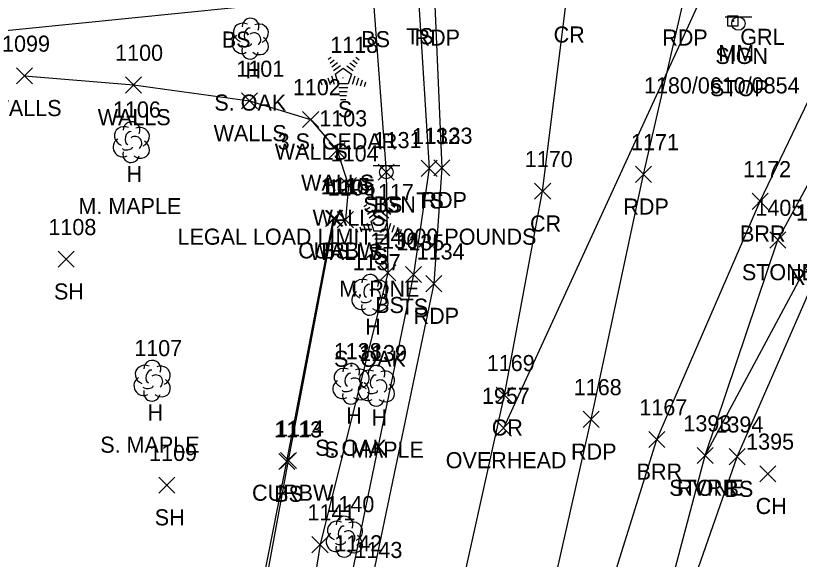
# Model space of a CAD drawing. Extents: x 1600395 to 1603269, y 874955 to 877143.
# Drawn here: x 1601626.7 to 1601724, y 875112.5 to 875180 of the extents above; entities that cross this region are included whole.
import ezdxf

# ---------------------------------------------------------------- set-up
doc = ezdxf.new("R2010")
doc.units = 0
for name, color, linetype in [('L_A', 7, 'Continuous'), ('L_C', 7, 'Continuous'), ('L_I', 7, 'Continuous'), ('L_TIC', 7, 'Continuous'), ('LABL', 7, 'Continuous'), ('LASF', 7, 'Continuous'), ('LAWE', 7, 'Continuous'), ('LELB', 7, 'Continuous'), ('LTC', 7, 'Continuous'), ('LTD', 7, 'Continuous'), ('LWS', 7, 'Continuous'), ('P_A', 7, 'Continuous'), ('P_I', 7, 'Continuous'), ('P_TIC', 7, 'Continuous'), ('PET', 7, 'Continuous'), ('PRC', 7, 'Continuous'), ('R_A', 7, 'Continuous'), ('R_I', 7, 'Continuous'), ('R_TIC', 7, 'Continuous'), ('RC', 7, 'Continuous'), ('S_A', 7, 'Continuous'), ('S_C', 7, 'Continuous'), ('S_I', 7, 'Continuous'), ('SRM', 7, 'Continuous'), ('SSGN', 7, 'Continuous'), ('U_A', 7, 'Continuous'), ('U_I', 7, 'Continuous'), ('U_TIC', 7, 'Continuous'), ('UCO', 7, 'Continuous')]:
    doc.layers.add(name, color=color, linetype=linetype)

msp = doc.modelspace()

# ---------------------------------------------------------------- linework, layer by layer
at = {"layer": 'L_TIC'}
for points in [[(1601626.758, 875171.562), (1601628.758, 875173.562)], [(1601628.758, 875171.562), (1601626.758, 875173.562)], [(1601640.32, 875170.433), (1601642.32, 875172.433)], [(1601642.32, 875170.433), (1601640.32, 875172.433)], [(1601654.724, 875168.448), (1601656.724, 875170.448)], [(1601656.724, 875168.448), (1601654.724, 875170.448)], [(1601662.315, 875166.155), (1601664.315, 875168.155)], [(1601664.315, 875166.155), (1601662.315, 875168.155)], [(1601665.592, 875162.288), (1601667.592, 875164.288)], [(1601667.592, 875162.288), (1601665.592, 875164.288)], [(1601677.04, 875160.078), (1601679.04, 875162.078)], [(1601679.04, 875160.078), (1601677.04, 875162.078)], [(1601671.7, 875159.584), (1601673.7, 875161.584)], [(1601673.7, 875159.584), (1601671.7, 875161.584)], [(1601667.016, 875157.931), (1601669.016, 875159.931)], [(1601669.016, 875157.931), (1601667.016, 875159.931)], [(1601718.177, 875155.975), (1601720.177, 875157.975)], [(1601720.177, 875155.975), (1601718.177, 875157.975)], [(1601665.176, 875153.849), (1601667.176, 875155.849)], [(1601667.176, 875153.849), (1601665.176, 875155.849)], [(1601666.628, 875153.693), (1601668.628, 875155.693)], [(1601668.628, 875153.693), (1601666.628, 875155.693)], [(1601720.351, 875151.173), (1601722.351, 875153.173)], [(1601722.351, 875151.173), (1601720.351, 875153.173)], [(1601631.943, 875148.778), (1601633.943, 875150.778)], [(1601633.943, 875148.778), (1601631.943, 875150.778)], [(1601671.894, 875147.092), (1601673.894, 875149.092)], [(1601673.894, 875147.092), (1601671.894, 875149.092)], [(1601675.089, 875146.885), (1601677.089, 875148.885)], [(1601677.089, 875146.885), (1601675.089, 875148.885)], [(1601705.335, 875126.39), (1601707.335, 875128.39)], [(1601707.335, 875126.39), (1601705.335, 875128.39)], [(1601711.321, 875124.386), (1601713.321, 875126.386)], [(1601713.321, 875124.386), (1601711.321, 875126.386)], [(1601711.321, 875124.386), (1601713.321, 875126.386)], [(1601713.321, 875124.386), (1601711.321, 875126.386)], [(1601715.306, 875124.249), (1601717.306, 875126.249)], [(1601717.306, 875124.249), (1601715.306, 875126.249)], [(1601659.345, 875123.636), (1601661.345, 875125.636)], [(1601661.345, 875123.636), (1601659.345, 875125.636)], [(1601719.123, 875122.124), (1601721.123, 875124.124)], [(1601721.123, 875122.124), (1601719.123, 875124.124)], [(1601644.462, 875120.714), (1601646.462, 875122.714)], [(1601646.462, 875120.714), (1601644.462, 875122.714)], [(1601663.484, 875113.32), (1601665.484, 875115.32)], [(1601665.484, 875113.32), (1601663.484, 875115.32)]]:
    msp.add_lwpolyline(points, dxfattribs=at)
at = {"layer": 'LABL'}
msp.add_lwpolyline([(1601678.037, 875019.801), (1601687.212, 875055.982), (1601695.924, 875094.108), (1601706.335, 875127.39), (1601719.177, 875156.975), (1601728.745, 875176.922)], dxfattribs=at)
at = {"layer": 'LASF'}
msp.add_lwpolyline([(1601712.321, 875125.386), (1601721.351, 875152.173), (1601739.232, 875185.072), (1601750.285, 875212.478), (1601747.91, 875211.652)], dxfattribs=at)
at = {"layer": 'LAWE'}
msp.add_lwpolyline([(1601691.608, 874961.829), (1601690.191, 874993.063), (1601689.233, 875017.016), (1601693.176, 875046.242), (1601698.322, 875069.371), (1601704.726, 875096.639), (1601712.321, 875125.386), (1601726.379, 875151.584), (1601742.355, 875184.332), (1601749.838, 875201.821), (1601757.17, 875214.811), (1601763.474, 875228.289), (1601769.619, 875241.931), (1601778.226, 875255.274), (1601780.685, 875261.68), (1601794.383, 875288.119), (1601816.126, 875319.133), (1601836.101, 875339.545), (1601856.898, 875374.373), (1601871.663, 875400.698), (1601886.602, 875430.708)], dxfattribs=at)
at = {"layer": 'LELB'}
for points in [[(1601699.549, 874960.018), (1601694.142, 874994.174), (1601691.323, 875016.49), (1601695.461, 875045.712), (1601700.163, 875068.941), (1601706.127, 875096.094), (1601716.306, 875125.249), (1601727.736, 875151.414), (1601744.118, 875184.771), (1601751.843, 875200.822), (1601755.991, 875200.418)], [(1601505.584, 875186.841), (1601543.498, 875188.163), (1601578.086, 875189.845), (1601619.87, 875193.155), (1601653.332, 875193.863), (1601668.347, 875196.112), (1601673.884, 875189.564), (1601676.765, 875181.488), (1601678.04, 875161.078), (1601676.089, 875147.885), (1601668.379, 875110.491), (1601657.668, 875076.04)], [(1601505.235, 875162.403), (1601544.115, 875168.6), (1601558.578, 875179.791), (1601582.314, 875176.109), (1601620.874, 875177.75), (1601653.84, 875181.076), (1601671.172, 875181.126), (1601672.7, 875160.584), (1601672.894, 875148.092), (1601664.484, 875114.32), (1601659.555, 875083.818), (1601652.568, 875078.374)], [(1601653.952, 875092.085), (1601660.345, 875124.636), (1601666.176, 875154.849)]]:
    msp.add_lwpolyline(points, dxfattribs=at)
at = {"layer": 'LTC'}
for p, q in [((1601665.513, 875174.625), (1601665.867, 875174.883)), ((1601668.911, 875174.865), (1601669.33, 875174.561)), ((1601665.722, 875174.16), (1601666.251, 875174.544)), ((1601665.932, 875173.694), (1601666.636, 875174.205)), ((1601666.141, 875173.228), (1601667.02, 875173.866)), ((1601667.798, 875173.82), (1601668.607, 875173.232)), ((1601668.169, 875174.169), (1601668.848, 875173.675)), ((1601668.54, 875174.517), (1601669.089, 875174.118)), ((1601666.366, 875172.773), (1601667.378, 875173.508)), ((1601666.366, 875172.773), (1601666.753, 875171.58)), ((1601667.378, 875173.508), (1601668.375, 875172.783)), ((1601668.375, 875172.783), (1601667.983, 875171.58)), ((1601664.545, 875171.904), (1601664.697, 875171.436)), ((1601665.001, 875172.121), (1601665.212, 875171.469)), ((1601665.456, 875172.338), (1601665.727, 875171.502)), ((1601665.911, 875172.554), (1601666.242, 875171.535)), ((1601668.812, 875172.512), (1601668.474, 875171.472)), ((1601669.257, 875172.261), (1601668.969, 875171.377)), ((1601669.701, 875172.011), (1601669.464, 875171.282)), ((1601670.146, 875171.761), (1601669.959, 875171.187)), ((1601667.983, 875171.58), (1601666.753, 875171.58)), ((1601667.945, 875171.08), (1601666.801, 875171.08)), ((1601667.861, 875170.58), (1601666.873, 875170.58)), ((1601667.778, 875170.08), (1601666.946, 875170.08)), ((1601667.694, 875169.58), (1601667.019, 875169.58)), ((1601669.943, 875156.33), (1601670.297, 875156.588)), ((1601670.152, 875155.865), (1601670.681, 875156.249)), ((1601672.97, 875156.223), (1601673.519, 875155.823)), ((1601673.341, 875156.571), (1601673.76, 875156.266)), ((1601670.362, 875155.399), (1601671.065, 875155.91)), ((1601670.571, 875154.933), (1601671.45, 875155.571)), ((1601670.796, 875154.478), (1601671.808, 875155.213)), ((1601671.808, 875155.213), (1601672.805, 875154.488)), ((1601672.228, 875155.526), (1601673.037, 875154.937)), ((1601672.599, 875155.874), (1601673.278, 875155.38)), ((1601670.341, 875154.259), (1601670.672, 875153.24)), ((1601670.796, 875154.478), (1601671.183, 875153.285)), ((1601672.805, 875154.488), (1601672.413, 875153.285)), ((1601668.975, 875153.61), (1601669.127, 875153.142)), ((1601669.43, 875153.826), (1601669.642, 875153.175)), ((1601669.886, 875154.043), (1601670.157, 875153.208)), ((1601672.413, 875153.285), (1601671.183, 875153.285)), ((1601673.242, 875154.217), (1601672.904, 875153.178)), ((1601673.687, 875153.967), (1601673.399, 875153.082)), ((1601674.131, 875153.717), (1601673.894, 875152.987)), ((1601674.575, 875153.466), (1601674.389, 875152.892)), ((1601672.375, 875152.785), (1601671.23, 875152.785)), ((1601672.291, 875152.285), (1601671.303, 875152.285)), ((1601672.208, 875151.785), (1601671.376, 875151.785)), ((1601672.124, 875151.285), (1601671.449, 875151.285))]:
    msp.add_line(p, q, dxfattribs=at)
at = {"layer": 'LTD'}
for p, q in [((1601655.801, 875177.242), (1601655.801, 875177.242)), ((1601655.801, 875177.242), (1601655.801, 875177.242)), ((1601641.015, 875164.38), (1601641.015, 875164.38)), ((1601641.015, 875164.38), (1601641.015, 875164.38)), ((1601670.668, 875145.412), (1601670.668, 875145.412)), ((1601670.668, 875145.412), (1601670.668, 875145.412)), ((1601643.606, 875134.738), (1601643.606, 875134.738)), ((1601643.606, 875134.738), (1601643.606, 875134.738)), ((1601668.316, 875134.359), (1601668.316, 875134.359)), ((1601668.316, 875134.359), (1601668.316, 875134.359)), ((1601671.464, 875134.121), (1601671.464, 875134.121)), ((1601671.464, 875134.121), (1601671.464, 875134.121)), ((1601667.49, 875115.361), (1601667.49, 875115.361)), ((1601667.49, 875115.361), (1601667.49, 875115.361))]:
    msp.add_line(p, q, dxfattribs=at)
for centre in [(1601655.848, 875178.676), (1601641.062, 875165.814), (1601670.715, 875146.845), (1601643.652, 875136.172), (1601668.362, 875135.793), (1601671.511, 875135.555), (1601667.537, 875116.795)]:
    msp.add_arc(centre, 1.047, 335.52715, 180.95627, dxfattribs=at)
for centre, major_axis, ratio, start_param, end_param in [((1601655.009, 875177.909), (1.21, -0.512), 0.895232, 1.570796, 4.712389), ((1601656.842, 875177.826), (-1.141, -0.483), 0.949671, 1.570796, 4.712389), ((1601655.592, 875177.7), (-0.208, -0.792), 0.645439, 3.141593, 6.283185), ((1601656.301, 875177.076), (-0.5, 0.667), 0.989748, 3.141593, 6.283185), ((1601654.718, 875176.534), (0.584, -1.042), 0.959034, 3.141593, 6.283185), ((1601656.801, 875176.409), (-1.09, 0.792), 0.841452, 1.570796, 4.712389), ((1601655.801, 875175.742), (0.265, 1.061), 0.942809, 1.570796, 4.712389), ((1601655.343, 875176.492), (-0.625, -0.083), 0.423636, 0, 3.141593), ((1601640.223, 875165.047), (1.21, -0.512), 0.895232, 1.570796, 4.712389), ((1601642.057, 875164.964), (-1.141, -0.483), 0.949671, 1.570796, 4.712389), ((1601640.807, 875164.838), (-0.208, -0.792), 0.645439, 3.141593, 6.283185), ((1601641.515, 875164.214), (-0.5, 0.667), 0.989748, 3.141593, 6.283185), ((1601639.932, 875163.672), (0.584, -1.042), 0.959034, 3.141593, 6.283185), ((1601642.015, 875163.547), (-1.09, 0.792), 0.841452, 1.570796, 4.712389), ((1601641.015, 875162.88), (0.265, 1.061), 0.942809, 1.570796, 4.712389), ((1601640.557, 875163.63), (-0.625, -0.083), 0.423636, 0, 3.141593), ((1601669.876, 875146.078), (1.21, -0.512), 0.895232, 1.570796, 4.712389), ((1601670.46, 875145.87), (-0.208, -0.792), 0.645439, 3.141593, 6.283185), ((1601671.71, 875145.995), (-1.141, -0.483), 0.949671, 1.570796, 4.712389), ((1601669.585, 875144.703), (0.584, -1.042), 0.959034, 3.141593, 6.283185), ((1601671.168, 875145.245), (-0.5, 0.667), 0.989748, 3.141593, 6.283185), ((1601671.668, 875144.578), (-1.09, 0.792), 0.841452, 1.570796, 4.712389), ((1601670.21, 875144.661), (-0.625, -0.083), 0.423636, 0, 3.141593), ((1601670.668, 875143.912), (0.265, 1.061), 0.942809, 1.570796, 4.712389), ((1601642.814, 875135.404), (1.21, -0.512), 0.895232, 1.570796, 4.712389), ((1601643.397, 875135.196), (-0.208, -0.792), 0.645439, 3.141593, 6.283185), ((1601644.647, 875135.321), (-1.141, -0.483), 0.949671, 1.570796, 4.712389), ((1601667.524, 875135.025), (1.21, -0.512), 0.895232, 1.570796, 4.712389), ((1601669.357, 875134.942), (-1.141, -0.483), 0.949671, 1.570796, 4.712389), ((1601670.672, 875134.787), (1.21, -0.512), 0.895232, 1.570796, 4.712389), ((1601672.506, 875134.704), (-1.141, -0.483), 0.949671, 1.570796, 4.712389), ((1601642.522, 875134.029), (0.584, -1.042), 0.959034, 3.141593, 6.283185), ((1601644.106, 875134.571), (-0.5, 0.667), 0.989748, 3.141593, 6.283185), ((1601644.606, 875133.905), (-1.09, 0.792), 0.841452, 1.570796, 4.712389), ((1601668.107, 875134.817), (-0.208, -0.792), 0.645439, 3.141593, 6.283185), ((1601668.816, 875134.192), (-0.5, 0.667), 0.989748, 3.141593, 6.283185), ((1601671.256, 875134.579), (-0.208, -0.792), 0.645439, 3.141593, 6.283185), ((1601671.964, 875133.954), (-0.5, 0.667), 0.989748, 3.141593, 6.283185), ((1601643.147, 875133.988), (-0.625, -0.083), 0.423636, 0, 3.141593), ((1601667.232, 875133.65), (0.584, -1.042), 0.959034, 3.141593, 6.283185), ((1601669.316, 875133.526), (-1.09, 0.792), 0.841452, 1.570796, 4.712389), ((1601670.381, 875133.412), (0.584, -1.042), 0.959034, 3.141593, 6.283185), ((1601672.464, 875133.288), (-1.09, 0.792), 0.841452, 1.570796, 4.712389), ((1601643.606, 875133.238), (0.265, 1.061), 0.942809, 1.570796, 4.712389), ((1601668.316, 875132.859), (0.265, 1.061), 0.942809, 1.570796, 4.712389), ((1601667.857, 875133.609), (-0.625, -0.083), 0.423636, 0, 3.141593), ((1601671.464, 875132.621), (0.265, 1.061), 0.942809, 1.570796, 4.712389), ((1601671.006, 875133.371), (-0.625, -0.083), 0.423636, 0, 3.141593), ((1601666.699, 875116.027), (1.21, -0.512), 0.895232, 1.570796, 4.712389), ((1601668.532, 875115.944), (-1.141, -0.483), 0.949671, 1.570796, 4.712389), ((1601667.282, 875115.819), (-0.208, -0.792), 0.645439, 3.141593, 6.283185), ((1601666.407, 875114.652), (0.584, -1.042), 0.959034, 3.141593, 6.283185), ((1601667.99, 875115.194), (-0.5, 0.667), 0.989748, 3.141593, 6.283185), ((1601668.49, 875114.528), (-1.09, 0.792), 0.841452, 1.570796, 4.712389), ((1601667.032, 875114.611), (-0.625, -0.083), 0.423636, 0, 3.141593), ((1601667.491, 875113.861), (0.265, 1.061), 0.942809, 1.570796, 4.712389)]:
    msp.add_ellipse(centre, major_axis=major_axis, ratio=ratio, start_param=start_param, end_param=end_param, dxfattribs=at)
at = {"layer": 'LWS'}
msp.add_lwpolyline([(1601627.758, 875172.562), (1601641.32, 875171.433), (1601655.724, 875169.448), (1601663.315, 875167.155), (1601666.592, 875163.288), (1601668.016, 875158.931), (1601667.628, 875154.693)], dxfattribs=at)
at = {"layer": 'P_TIC'}
for points in [[(1601678.602, 875160.131), (1601680.602, 875162.131)], [(1601680.602, 875160.131), (1601678.602, 875162.131)], [(1601703.679, 875159.327), (1601705.679, 875161.327)], [(1601705.679, 875159.327), (1601703.679, 875161.327)], [(1601691.14, 875157.223), (1601693.14, 875159.223)], [(1601693.14, 875157.223), (1601691.14, 875159.223)], [(1601677.619, 875145.746), (1601679.619, 875147.746)], [(1601679.619, 875145.746), (1601677.619, 875147.746)], [(1601686.383, 875131.88), (1601688.383, 875133.88)], [(1601688.383, 875131.88), (1601686.383, 875133.88)], [(1601697.183, 875128.886), (1601699.183, 875130.886)], [(1601699.183, 875128.886), (1601697.183, 875130.886)]]:
    msp.add_lwpolyline(points, dxfattribs=at)
at = {"layer": 'PET'}
for points in [[(1601673.093, 875021.696), (1601681.133, 875058.084), (1601690.373, 875095.308), (1601698.183, 875129.886), (1601704.679, 875160.327), (1601709.513, 875181.324), (1601714.923, 875193.415), (1601721.533, 875203.075), (1601729.108, 875210.606), (1601733.529, 875213.857), (1601739.733, 875217.719)], [(1601655.314, 875206.252), (1601666.285, 875201.032), (1601673.685, 875194.463), (1601676.806, 875189.048), (1601678.738, 875181.317), (1601679.602, 875161.131), (1601678.619, 875146.746), (1601670.887, 875109.659), (1601661.849, 875070.373), (1601658.601, 875056.472), (1601651.571, 875026.414)]]:
    msp.add_lwpolyline(points, dxfattribs=at)
at = {"layer": 'PRC'}
msp.add_lwpolyline([(1601662.483, 875023.749), (1601671.39, 875061.762), (1601679.377, 875096.605), (1601687.383, 875132.88), (1601692.14, 875158.223), (1601695.071, 875181.696), (1601696.102, 875195.085), (1601696.172, 875205.464), (1601695.275, 875211.435)], dxfattribs=at)
at = {"layer": 'R_TIC'}
for points in [[(1601665.298, 875153.875), (1601667.298, 875155.875)], [(1601667.298, 875153.875), (1601665.298, 875155.875)], [(1601659.569, 875123.77), (1601661.569, 875125.77)], [(1601661.569, 875123.77), (1601659.569, 875125.77)]]:
    msp.add_lwpolyline(points, dxfattribs=at)
at = {"layer": 'RC'}
msp.add_lwpolyline([(1601654.529, 875091.918), (1601660.569, 875124.77), (1601666.298, 875154.875)], dxfattribs=at)
at = {"layer": 'SRM'}
msp.add_lwpolyline([(1601715.157, 875180.006), (1601716.407, 875180.006), (1601716.407, 875178.756), (1601715.157, 875178.756)], close=True, dxfattribs=at)
msp.add_circle((1601715.782, 875179.381), 0.0833, dxfattribs=at)
at = {"layer": 'SSGN'}
for p, q in [((1601714.816, 875179.892), (1601718.149, 875179.892)), ((1601716.463, 875179.059), (1601716.463, 875179.059)), ((1601671.072, 875161.438), (1601674.406, 875161.438)), ((1601672.719, 875160.605), (1601672.719, 875160.605))]:
    msp.add_line(p, q, dxfattribs=at)
for centre in [(1601716.463, 875179.059), (1601672.719, 875160.605)]:
    msp.add_circle(centre, 0.833, dxfattribs=at)
at = {"layer": 'U_TIC'}
for points in [[(1601686.29, 875127.811), (1601688.29, 875129.811)], [(1601688.29, 875127.811), (1601686.29, 875129.811)]]:
    msp.add_lwpolyline(points, dxfattribs=at)
at = {"layer": 'UCO'}
msp.add_lwpolyline([(1601739.016, 875246.802), (1601721.199, 875202.682), (1601687.29, 875128.811)], dxfattribs=at)

# ---------------------------------------------------------------- texts
at = {"layer": 'L_A'}
for s, p in [('BS', (1601652.281, 875176.076)), ('BS', (1601669.613, 875176.126)), ('TS', (1601675.175, 875176.488)), ('H', (1601655.234, 875172.242)), ('WALLS', (1601623.302, 875167.562)), ('S', (1601666.703, 875167.417)), ('WALLS', (1601636.863, 875166.433)), ('WALLS', (1601651.267, 875164.448)), ('WALLS', (1601658.858, 875162.155)), ('H', (1601640.448, 875159.38)), ('WALLS', (1601662.136, 875158.288)), ('BS', (1601671.141, 875155.584)), ('TS', (1601676.449, 875156.078)), ('WALLS', (1601663.56, 875153.931)), ('BRR', (1601716.665, 875151.975)), ('WALLS', (1601663.172, 875149.693)), ('BS', (1601664.617, 875149.849)), ('S', (1601671.133, 875149.122)), ('STONE', (1601716.895, 875147.173)), ('RVRR', (1601722.891, 875146.584)), ('SH', (1601631.431, 875144.778)), ('BS', (1601671.335, 875143.092)), ('TS', (1601674.498, 875142.885)), ('H', (1601670.101, 875140.412)), ('H', (1601643.039, 875129.738)), ('H', (1601667.749, 875129.359)), ('H', (1601670.897, 875129.121)), ('BRR', (1601703.823, 875122.39)), ('STONE', (1601707.865, 875120.386)), ('RVRR', (1601708.833, 875120.386)), ('BS', (1601714.747, 875120.249)), ('BS', (1601658.786, 875119.636)), ('CH', (1601718.611, 875118.124)), ('SH', (1601643.95, 875116.714))]:
    msp.add_text(s, height=2, dxfattribs=at).set_placement(p)
at = {"layer": 'L_C'}
for s, p in [('S. OAK', (1601651.36, 875168.242)), ('3 S. CEDAR', (1601659.215, 875163.417)), ('M. MAPLE', (1601634.464, 875155.38)), ('LEGAL LOAD LIMIT 24000 POUNDS', (1601646.779, 875151.584)), ('M. PINE', (1601666.866, 875145.122)), ('S. OAK', (1601666.227, 875136.412)), ('S. MAPLE', (1601637.181, 875125.738)), ('S. OAK', (1601663.875, 875125.359)), ('S. MAPLE', (1601665.039, 875125.121))]:
    msp.add_text(s, height=2, dxfattribs=at).set_placement(p)
at = {"layer": 'L_I'}
for s, p in [('1099', (1601624.979, 875175.562)), ('1118', (1601665.759, 875175.417)), ('1100', (1601639.029, 875174.433)), ('1101', (1601654.086, 875172.448)), ('1102', (1601661.11, 875170.155)), ('1106', (1601638.756, 875167.38)), ('1103', (1601664.388, 875166.288)), ('1132', (1601675.914, 875164.078)), ('1131', (1601671.141, 875163.584)), ('1104', (1601665.812, 875161.931)), ('1172', (1601717.051, 875159.975)), ('1116', (1601664.563, 875157.849)), ('1105', (1601665.424, 875157.693)), ('1117', (1601670.189, 875157.122)), ('1405', (1601718.58, 875155.173)), ('1404', (1601723.608, 875154.584)), ('1108', (1601630.739, 875152.778)), ('1136', (1601670.713, 875151.092)), ('1135', (1601673.963, 875150.885)), ('1137', (1601668.542, 875148.412)), ('1107', (1601641.401, 875137.738)), ('1138', (1601666.19, 875137.359)), ('1139', (1601669.331, 875137.121)), ('1167', (1601704.162, 875130.39)), ('1393', (1601709.629, 875128.386)), ('1393', (1601709.629, 875128.386)), ('1394', (1601713.613, 875128.249)), ('1113', (1601658.786, 875127.636)), ('1395', (1601717.43, 875126.124)), ('1109', (1601643.25, 875124.714)), ('1140', (1601665.278, 875118.361)), ('1141', (1601662.925, 875117.32)), ('1142', (1601666.253, 875113.491))]:
    msp.add_text(s, height=2, dxfattribs=at).set_placement(p)
at = {"layer": 'LTC'}
for p in [(1601667.26, 875172.521), (1601671.69, 875154.226)]:
    msp.add_text('.', height=1.037, rotation=270, dxfattribs=at).set_placement(p)
at = {"layer": 'P_A'}
for s, p in [('CR', (1601693.504, 875176.696)), ('RDP', (1601676.226, 875176.317)), ('RDP', (1601707.001, 875176.324)), ('RDP', (1601677.09, 875156.131)), ('RDP', (1601702.167, 875155.327)), ('CR', (1601690.573, 875153.223)), ('RDP', (1601676.107, 875141.746)), ('CR', (1601685.816, 875127.88)), ('RDP', (1601695.672, 875124.886))]:
    msp.add_text(s, height=2, dxfattribs=at).set_placement(p)
at = {"layer": 'P_I'}
for s, p in [('1133', (1601677.476, 875164.131)), ('1171', (1601703.12, 875163.327)), ('1170', (1601689.927, 875161.223)), ('1134', (1601676.493, 875149.746)), ('1169', (1601685.203, 875135.88)), ('1168', (1601696.01, 875132.886)), ('1143', (1601668.761, 875112.659))]:
    msp.add_text(s, height=2, dxfattribs=at).set_placement(p)
at = {"layer": 'R_A'}
for s, p in [('GRL', (1601716.697, 875176.414)), ('CURBW', (1601661.763, 875149.875)), ('CURBW', (1601656.034, 875119.77))]:
    msp.add_text(s, height=2, dxfattribs=at).set_placement(p)
at = {"layer": 'R_I'}
for s, p in [('1115', (1601664.739, 875157.875)), ('1114', (1601659.01, 875127.77))]:
    msp.add_text(s, height=2, dxfattribs=at).set_placement(p)
at = {"layer": 'S_A'}
for s, p in [('SIGN', (1601713.601, 875174.039)), ('MM', (1601713.971, 875174.381)), ('SIGN', (1601669.857, 875155.584))]:
    msp.add_text(s, height=2, dxfattribs=at).set_placement(p)
at = {"layer": 'S_C'}
for s, p in [('1180/0610/0854', (1601704.727, 875170.381)), ('STOP', (1601712.924, 875170.039))]:
    msp.add_text(s, height=2, dxfattribs=at).set_placement(p)
at = {"layer": 'S_I'}
msp.add_text('1131', height=2, dxfattribs=at).set_placement((1601671.141, 875163.584))
at = {"layer": 'U_A'}
msp.add_text('OVERHEAD', height=2, dxfattribs=at).set_placement((1601680.101, 875123.811))
at = {"layer": 'U_I'}
msp.add_text('1957', height=2, dxfattribs=at).set_placement((1601684.597, 875131.811))

doc.saveas('drawing.dxf')
